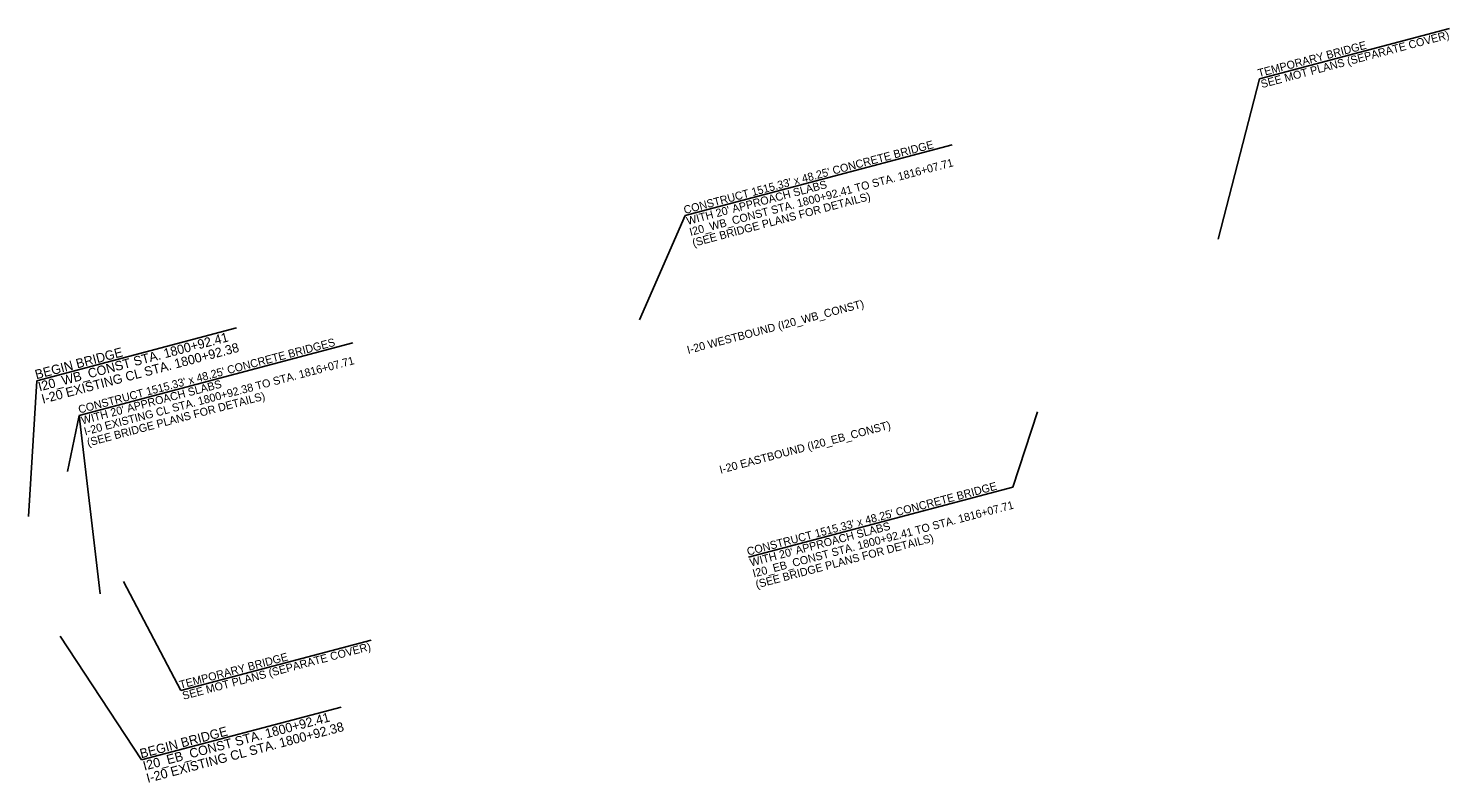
# Model space of a CAD drawing. Extents: x 2110155 to 2114862, y 866944 to 868497.
# Drawn here: x 2111203 to 2112268, y 867297 to 867862 of the extents above; entities that cross this region are included whole.
import ezdxf

# ---------------------------------------------------------------- set-up
doc = ezdxf.new("R2010")
doc.units = 0
doc.layers.add('RD_SHT_Bndy', color=7, linetype='Continuous')

msp = doc.modelspace()

# ---------------------------------------------------------------- linework, layer by layer
at = {"layer": 'RD_SHT_Bndy'}
for p, q in [((2112268.1, 867862), (2112125.7, 867824.2)), ((2111895.4, 867774.7), (2111695.2, 867721.6)), ((2111358.7, 867637.4), (2111209.1, 867597.7)), ((2111445.9, 867626.2), (2111240.9, 867571.8)), ((2111256.5, 867438.1), (2111240.9, 867571.8)), ((2111940.8, 867518), (2111742.5, 867465.5)), ((2111459.7, 867403.4), (2111317.2, 867365.6)), ((2111437.3, 867353.1), (2111287.7, 867313.5))]:
    msp.add_line(p, q, dxfattribs=at)
for points in [[(2112125.7, 867824.2), (2112094.8, 867704.1)], [(2111695.2, 867721.6), (2111660.9, 867643.5)], [(2111209.1, 867597.7), (2111202.8, 867496.1)], [(2111940.8, 867518), (2111959.3, 867574.4)], [(2111240.9, 867571.8), (2111232.2, 867529.9)], [(2111317.2, 867365.6), (2111274.1, 867447.3)], [(2111287.7, 867313.5), (2111226.7, 867406.2)]]:
    msp.add_lwpolyline(points, dxfattribs=at)

# ---------------------------------------------------------------- texts
for s, height, p in [('TEMPORARY BRIDGE', 6, (2112125.3, 867825.4)), ('SEE MOT PLANS (SEPARATE COVER)', 6, (2112127.5, 867817.2)), ("CONSTRUCT 1515.33' x 48.25' CONCRETE BRIDGE", 6, (2111694.9, 867722.8)), ('I20_WB_CONST STA. 1800+92.41 TO STA. 1816+07.71', 6, (2111699.2, 867706.4)), ("WITH 20' APPROACH SLABS", 6, (2111697, 867714.6)), ('(SEE BRIDGE PLANS FOR DETAILS)', 6, (2111701.4, 867698.2)), ('I-20 WESTBOUND (I20_WB_CONST)', 6, (2111697.4, 867617.9)), ('I20_WB_CONST STA. 1800+92.41', 7, (2111211.2, 867589.8)), ("CONSTRUCT 1515.33' x 48.25' CONCRETE BRIDGES", 6, (2111241.1, 867573.2)), ('BEGIN BRIDGE', 7, (2111208.8, 867598.9)), ('I-20 EXISTING CL STA. 1800+92.38', 7, (2111213.7, 867580.6)), ('I-20 EXISTING CL STA. 1800+92.38 TO STA. 1816+07.71', 6, (2111245.4, 867556.8)), ("WITH 20' APPROACH SLABS", 6, (2111243.3, 867565)), ('(SEE BRIDGE PLANS FOR DETAILS)', 6, (2111247.6, 867548.5)), ('I-20 EASTBOUND (I20_EB_CONST)', 6, (2111721.7, 867528.1)), ("CONSTRUCT 1515.33' x 48.25' CONCRETE BRIDGE", 6, (2111742.3, 867466.7)), ('I20_EB_CONST STA. 1800+92.41 TO STA. 1816+07.71', 6, (2111746.6, 867450.3)), ("WITH 20' APPROACH SLABS", 6, (2111744.5, 867458.5)), ('(SEE BRIDGE PLANS FOR DETAILS)', 6, (2111748.8, 867442.1)), ('TEMPORARY BRIDGE', 6, (2111316.9, 867366.8)), ('SEE MOT PLANS (SEPARATE COVER)', 6, (2111319.1, 867358.6)), ('I20_EB_CONST STA. 1800+92.41', 7, (2111289.8, 867305.5)), ('I-20 EXISTING CL STA. 1800+92.38', 7, (2111292.3, 867296.3)), ('BEGIN BRIDGE', 7, (2111287.4, 867314.7))]:
    msp.add_text(s, height=height, rotation=14.8448, dxfattribs=at).set_placement(p)

doc.saveas('drawing.dxf')
